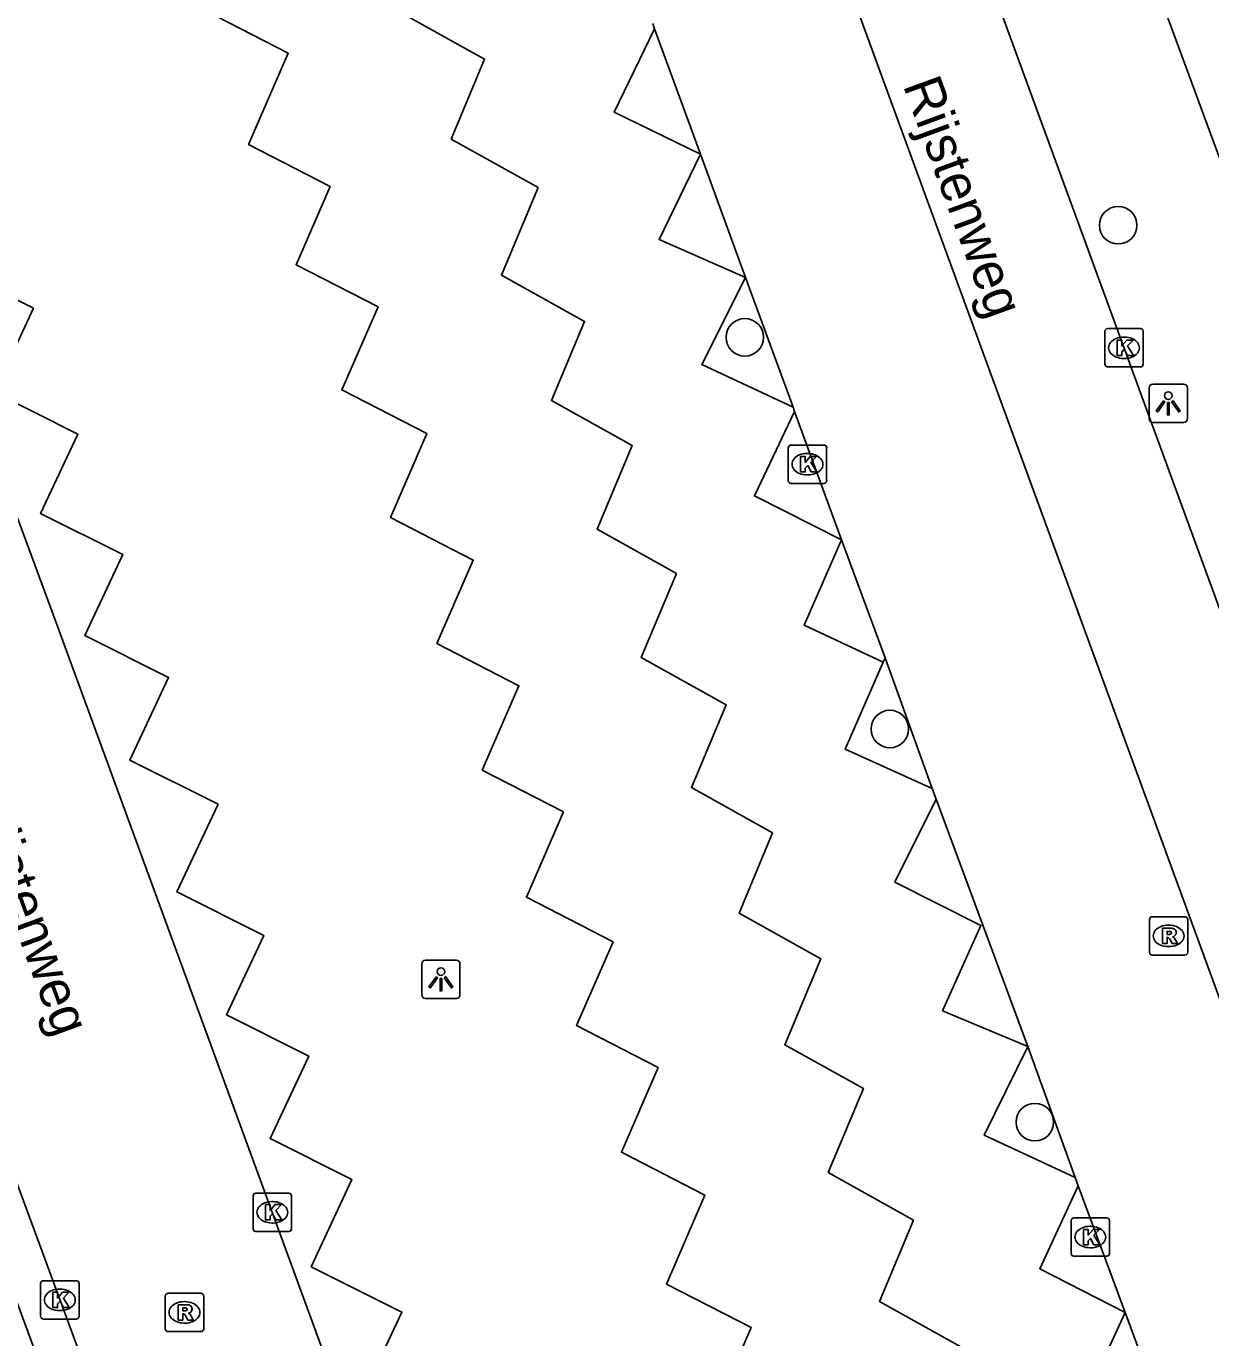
# Model space of a CAD drawing. Extents: x 158087 to 159494, y 382905 to 383981.
# Drawn here: x 159009.25 to 159040.12, y 383055.22 to 383089.39 of the extents above; entities that cross this region are included whole.
import ezdxf

# ---------------------------------------------------------------- set-up
doc = ezdxf.new("R2010")
doc.units = 0
for name, color, linetype in [('IMGEO_Boom', 7, 'Continuous'), ('IMGEO_Fietspad_gesloten', 7, 'Continuous'), ('IMGEO_Haag', 7, 'Continuous'), ('IMGEO_Kolk', 7, 'Continuous'), ('IMGEO_Lichtpunt', 7, 'Continuous'), ('IMGEO_Openbare_ruimte_label', 7, 'Continuous'), ('IMGEO_Parkeervlak_open', 7, 'Continuous'), ('IMGEO_Rijbaan_lokaal_open', 7, 'Continuous'), ('IMGEO_Rioolput', 7, 'Continuous'), ('IMGEO_Voetpad_open', 7, 'Continuous')]:
    doc.layers.add(name, color=color, linetype=linetype)

msp = doc.modelspace()

# ---------------------------------------------------------------- linework, layer by layer
at = {"layer": 'IMGEO_Boom'}
for centre in [(159037.708, 383084.203), (159027.977, 383081.283), (159031.757, 383071.077), (159035.537, 383060.834)]:
    msp.add_circle(centre, 0.489, dxfattribs=at)
at = {"layer": 'IMGEO_Fietspad_gesloten'}
for points in [[(159019.008, 383132.479), (159054.763, 383034.863)], [(159015.626, 383131.206), (159027.244, 383099.827), (159051.483, 383033.66)]]:
    msp.add_lwpolyline(points, dxfattribs=at)
at = {"layer": 'IMGEO_Haag'}
for points in [[(159027.998, 383082.843), (159029.233, 383079.462)], [(159031.633, 383072.927), (159032.862, 383069.528)], [(159035.352, 383062.802), (159036.584, 383059.388)]]:
    msp.add_lwpolyline(points, dxfattribs=at)
at = {"layer": 'IMGEO_Kolk'}
for p, q in [((159037.359, 383080.584), (159037.359, 383081.436)), ((159037.434, 383081.51), (159038.286, 383081.51)), ((159038.36, 383081.436), (159038.36, 383080.584)), ((159037.847, 383081.29), (159037.872, 383081.29)), ((159037.87, 383080.73), (159037.845, 383080.73)), ((159038.286, 383080.51), (159037.434, 383080.51)), ((159029.109, 383077.55), (159029.109, 383078.402)), ((159029.184, 383078.476), (159030.036, 383078.476)), ((159030.11, 383078.402), (159030.11, 383077.55)), ((159029.597, 383078.256), (159029.622, 383078.256)), ((159029.62, 383077.696), (159029.595, 383077.696)), ((159030.036, 383077.476), (159029.184, 383077.476)), ((159015.162, 383058.058), (159015.162, 383058.91)), ((159015.237, 383058.984), (159016.089, 383058.984)), ((159016.163, 383058.91), (159016.163, 383058.058)), ((159015.65, 383058.764), (159015.675, 383058.764)), ((159015.673, 383058.204), (159015.648, 383058.204)), ((159036.481, 383057.414), (159036.481, 383058.266)), ((159036.556, 383058.34), (159037.408, 383058.34)), ((159036.969, 383058.12), (159036.994, 383058.12)), ((159037.482, 383058.266), (159037.482, 383057.414)), ((159016.089, 383057.984), (159015.237, 383057.984)), ((159036.992, 383057.56), (159036.967, 383057.56)), ((159037.408, 383057.34), (159036.556, 383057.34)), ((159009.624, 383055.776), (159009.624, 383056.628)), ((159009.699, 383056.702), (159010.551, 383056.702)), ((159010.112, 383056.482), (159010.137, 383056.482)), ((159010.625, 383056.628), (159010.625, 383055.776)), ((159010.135, 383055.922), (159010.11, 383055.922)), ((159010.551, 383055.702), (159009.699, 383055.702))]:
    msp.add_line(p, q, dxfattribs=at)
for points in [[(159037.359, 383080.584), (159037.359, 383081.436)], [(159037.434, 383081.51), (159038.286, 383081.51)], [(159038.36, 383081.436), (159038.36, 383080.584)], [(159037.68, 383081.21), (159037.803, 383081.21), (159037.803, 383081.059), (159037.933, 383081.21), (159038.097, 383081.21), (159037.951, 383081.059), (159038.104, 383080.81), (159037.952, 383080.81), (159037.867, 383080.974), (159037.803, 383080.907), (159037.803, 383080.81), (159037.68, 383080.81), (159037.68, 383081.21)], [(159038.286, 383080.51), (159037.434, 383080.51)], [(159029.109, 383077.55), (159029.109, 383078.402)], [(159029.184, 383078.476), (159030.036, 383078.476)], [(159030.11, 383078.402), (159030.11, 383077.55)], [(159029.43, 383078.176), (159029.553, 383078.176), (159029.553, 383078.025), (159029.683, 383078.176), (159029.847, 383078.176), (159029.701, 383078.025), (159029.854, 383077.776), (159029.702, 383077.776), (159029.617, 383077.94), (159029.553, 383077.873), (159029.553, 383077.776), (159029.43, 383077.776), (159029.43, 383078.176)], [(159030.036, 383077.476), (159029.184, 383077.476)], [(159015.162, 383058.058), (159015.162, 383058.91)], [(159015.237, 383058.984), (159016.089, 383058.984)], [(159016.163, 383058.91), (159016.163, 383058.058)], [(159015.483, 383058.684), (159015.606, 383058.684), (159015.606, 383058.533), (159015.736, 383058.684), (159015.9, 383058.684), (159015.754, 383058.533), (159015.907, 383058.284), (159015.755, 383058.284), (159015.67, 383058.448), (159015.606, 383058.381), (159015.606, 383058.284), (159015.483, 383058.284), (159015.483, 383058.684)], [(159036.481, 383057.414), (159036.481, 383058.266)], [(159036.556, 383058.34), (159037.408, 383058.34)], [(159037.482, 383058.266), (159037.482, 383057.414)], [(159016.089, 383057.984), (159015.237, 383057.984)], [(159036.802, 383058.04), (159036.925, 383058.04), (159036.925, 383057.889), (159037.055, 383058.04), (159037.219, 383058.04), (159037.073, 383057.889), (159037.226, 383057.64), (159037.074, 383057.64), (159036.989, 383057.804), (159036.925, 383057.737), (159036.925, 383057.64), (159036.802, 383057.64), (159036.802, 383058.04)], [(159037.408, 383057.34), (159036.556, 383057.34)], [(159009.624, 383055.776), (159009.624, 383056.628)], [(159009.699, 383056.702), (159010.551, 383056.702)], [(159010.625, 383056.628), (159010.625, 383055.776)], [(159009.945, 383056.402), (159010.068, 383056.402), (159010.068, 383056.251), (159010.198, 383056.402), (159010.362, 383056.402), (159010.216, 383056.251), (159010.369, 383056.002), (159010.217, 383056.002), (159010.132, 383056.166), (159010.068, 383056.099), (159010.068, 383056.002), (159009.945, 383056.002), (159009.945, 383056.402)], [(159010.551, 383055.702), (159009.699, 383055.702)]]:
    msp.add_lwpolyline(points, dxfattribs=at)
for centre, start, end in [((159037.436, 383081.434), 91.552, 178.448), ((159037.436, 383081.434), 91.552, 178.448), ((159038.284, 383081.434), 1.552, 88.448), ((159038.284, 383081.434), 1.552, 88.448), ((159037.436, 383080.586), 181.552, 268.448), ((159037.436, 383080.586), 181.552, 268.448), ((159038.284, 383080.586), 271.552, 358.448), ((159038.284, 383080.586), 271.552, 358.448), ((159029.186, 383078.4), 91.552, 178.448), ((159029.186, 383078.4), 91.552, 178.448), ((159030.034, 383078.4), 1.552, 88.448), ((159030.034, 383078.4), 1.552, 88.448), ((159029.186, 383077.552), 181.552, 268.448), ((159029.186, 383077.552), 181.552, 268.448), ((159030.034, 383077.552), 271.552, 358.448), ((159030.034, 383077.552), 271.552, 358.448), ((159015.239, 383058.908), 91.552, 178.448), ((159015.239, 383058.908), 91.552, 178.448), ((159016.087, 383058.908), 1.552, 88.448), ((159016.087, 383058.908), 1.552, 88.448), ((159036.558, 383058.264), 91.552, 178.448), ((159036.558, 383058.264), 91.552, 178.448), ((159037.406, 383058.264), 1.552, 88.448), ((159037.406, 383058.264), 1.552, 88.448), ((159015.239, 383058.06), 181.552, 268.448), ((159015.239, 383058.06), 181.552, 268.448), ((159016.087, 383058.06), 271.552, 358.448), ((159016.087, 383058.06), 271.552, 358.448), ((159036.558, 383057.416), 181.552, 268.448), ((159036.558, 383057.416), 181.552, 268.448), ((159037.406, 383057.416), 271.552, 358.448), ((159037.406, 383057.416), 271.552, 358.448), ((159009.701, 383056.626), 91.552, 178.448), ((159009.701, 383056.626), 91.552, 178.448), ((159010.549, 383056.626), 1.552, 88.448), ((159010.549, 383056.626), 1.552, 88.448), ((159009.701, 383055.778), 181.552, 268.448), ((159009.701, 383055.778), 181.552, 268.448), ((159010.549, 383055.778), 271.552, 358.448), ((159010.549, 383055.778), 271.552, 358.448)]:
    msp.add_arc(centre, 0.0765, start, end, dxfattribs=at)
for centre, major_axis, ratio, start_param, end_param in [((159037.846, 383081.01), (-0.387, 0.002), 0.722429, 4.712389, 7.853982), ((159037.871, 383081.01), (-0.39, 0.002), 0.717154, 1.570796, 4.712389), ((159029.596, 383077.976), (-0.387, 0.002), 0.722429, 4.712389, 7.853982), ((159029.621, 383077.976), (-0.39, 0.002), 0.717154, 1.570796, 4.712389), ((159015.649, 383058.484), (-0.387, 0.002), 0.722429, 4.712389, 7.853982), ((159015.674, 383058.484), (-0.39, 0.002), 0.717154, 1.570796, 4.712389), ((159036.968, 383057.84), (-0.387, 0.002), 0.722429, 4.712389, 7.853982), ((159036.993, 383057.84), (-0.39, 0.002), 0.717154, 1.570796, 4.712389), ((159010.111, 383056.202), (-0.387, 0.002), 0.722429, 4.712389, 7.853982), ((159010.136, 383056.202), (-0.39, 0.002), 0.717154, 1.570796, 4.712389)]:
    msp.add_ellipse(centre, major_axis=major_axis, ratio=ratio, start_param=start_param, end_param=end_param, dxfattribs=at)
at = {"layer": 'IMGEO_Lichtpunt'}
for p, q in [((159039.417, 383080.06), (159038.609, 383080.06)), ((159039.417, 383080.06), (159038.609, 383080.06)), ((159038.515, 383079.965), (159038.515, 383079.158)), ((159038.515, 383079.965), (159038.515, 383079.158)), ((159039.511, 383079.158), (159039.511, 383079.965)), ((159039.511, 383079.158), (159039.511, 383079.965)), ((159038.609, 383079.064), (159039.417, 383079.064)), ((159038.609, 383079.064), (159039.417, 383079.064)), ((159019.557, 383064.958), (159019.557, 383064.151)), ((159019.557, 383064.958), (159019.557, 383064.151)), ((159020.459, 383065.053), (159019.651, 383065.053)), ((159020.459, 383065.053), (159019.651, 383065.053)), ((159020.553, 383064.151), (159020.553, 383064.958)), ((159020.553, 383064.151), (159020.553, 383064.958)), ((159019.651, 383064.057), (159020.459, 383064.057)), ((159019.651, 383064.057), (159020.459, 383064.057))]:
    msp.add_line(p, q, dxfattribs=at)
for points in [[(159038.889, 383079.629), (159038.928, 383079.601), (159038.74, 383079.339), (159038.702, 383079.366), (159038.889, 383079.629)], [(159038.991, 383079.581), (159039.038, 383079.581), (159039.038, 383079.259), (159038.991, 383079.259), (159038.991, 383079.581)], [(159039.101, 383079.601), (159039.139, 383079.628), (159039.326, 383079.366), (159039.287, 383079.338), (159039.101, 383079.601)], [(159019.931, 383064.622), (159019.97, 383064.594), (159019.782, 383064.332), (159019.744, 383064.359), (159019.931, 383064.622)], [(159020.143, 383064.594), (159020.181, 383064.621), (159020.368, 383064.359), (159020.329, 383064.331), (159020.143, 383064.594)], [(159020.033, 383064.574), (159020.08, 383064.574), (159020.08, 383064.252), (159020.033, 383064.252), (159020.033, 383064.574)]]:
    msp.add_lwpolyline(points, dxfattribs=at)
for centre in [(159039.014, 383079.763), (159020.056, 383064.756)]:
    msp.add_circle(centre, 0.0994, dxfattribs=at)
for centre, start, end in [((159038.609, 383079.965), 90, 180), ((159038.609, 383079.965), 90, 180), ((159039.417, 383079.965), 0, 90), ((159039.417, 383079.965), 0, 90), ((159038.609, 383079.158), 180, 270), ((159038.609, 383079.158), 180, 270), ((159039.417, 383079.158), 270, 0), ((159039.417, 383079.158), 270, 360), ((159019.651, 383064.958), 90, 180), ((159019.651, 383064.958), 90, 180), ((159020.459, 383064.958), 0, 90), ((159020.459, 383064.958), 0, 90), ((159019.651, 383064.151), 180, 270), ((159019.651, 383064.151), 180, 270), ((159020.459, 383064.151), 270, 0), ((159020.459, 383064.151), 270, 360)]:
    msp.add_arc(centre, 0.0946, start, end, dxfattribs=at)
at = {"layer": 'IMGEO_Parkeervlak_open'}
for points in [[(159025.576, 383089.458), (159025.627, 383089.318)], [(159027.998, 383082.843), (159026.854, 383080.574), (159029.233, 383079.462)], [(159029.233, 383079.462), (159029.273, 383079.352)], [(159031.587, 383072.822), (159030.589, 383070.553), (159032.862, 383069.528)], [(159032.862, 383069.528), (159032.965, 383069.25)], [(159035.352, 383062.802), (159034.218, 383060.491), (159036.584, 383059.388)], [(159036.584, 383059.388), (159036.663, 383059.174)]]:
    msp.add_lwpolyline(points, dxfattribs=at)
at = {"layer": 'IMGEO_Rijbaan_lokaal_open'}
for points in [[(158989.496, 383130.166), (158989.507, 383130.115), (158993.547, 383118.852), (159000, 383101.106), (159000.486, 383099.77), (159004.399, 383089.064), (159010.016, 383073.897), (159017.762, 383052.749), (159024.745, 383033.951), (159029.515, 383020.822)], [(159013.895, 383089.803), (159016.076, 383088.683), (159015.043, 383086.305), (159017.17, 383085.212), (159016.284, 383083.174), (159018.417, 383082.078), (159017.476, 383079.913), (159019.693, 383078.774), (159018.743, 383076.588), (159020.899, 383075.48), (159019.952, 383073.302), (159022.089, 383072.204), (159021.133, 383070.005), (159023.25, 383068.917), (159022.283, 383066.694), (159024.543, 383065.533), (159023.593, 383063.348), (159025.723, 383062.254), (159024.764, 383060.048), (159026.939, 383058.931), (159025.933, 383056.616), (159028.145, 383055.48), (159027.183, 383053.267)], [(159033.687, 383054.933), (159031.485, 383056.162), (159032.372, 383058.28), (159030.15, 383059.52), (159031.066, 383061.707), (159029.019, 383062.849), (159029.958, 383065.091), (159027.826, 383066.28), (159028.701, 383068.369), (159026.584, 383069.55), (159027.488, 383071.708), (159025.28, 383072.94), (159026.196, 383075.127), (159024.129, 383076.28), (159025.042, 383078.461), (159022.938, 383079.635), (159023.801, 383081.695), (159021.636, 383082.903), (159022.591, 383085.183), (159020.324, 383086.448), (159021.195, 383088.528), (159019.1, 383089.697)], [(159018.031, 383053.735), (159019.04, 383055.883), (159016.672, 383057.067), (159017.738, 383059.337), (159015.604, 383060.404), (159016.614, 383062.556), (159014.469, 383063.629), (159015.441, 383065.7), (159013.175, 383066.833), (159014.248, 383069.118), (159011.947, 383070.269), (159012.957, 383072.42), (159010.773, 383073.512), (159011.765, 383075.625), (159009.624, 383076.695), (159010.595, 383078.763), (159008.409, 383079.856), (159009.435, 383082.042), (159007.189, 383083.165)], [(159019.666, 383030.258), (159014.295, 383044.868), (159010.659, 383054.753), (159005.874, 383067.711), (159001.376, 383079.933)]]:
    msp.add_lwpolyline(points, dxfattribs=at)
at = {"layer": 'IMGEO_Rioolput'}
for p, q in [((159038.522, 383065.26), (159038.522, 383066.112)), ((159038.597, 383066.186), (159039.449, 383066.186)), ((159039.523, 383066.112), (159039.523, 383065.26)), ((159039.01, 383065.966), (159039.035, 383065.966)), ((159039.033, 383065.406), (159039.008, 383065.406)), ((159039.449, 383065.186), (159038.597, 383065.186)), ((159012.873, 383055.451), (159012.873, 383056.303)), ((159012.948, 383056.377), (159013.8, 383056.377)), ((159013.361, 383056.157), (159013.386, 383056.157)), ((159013.874, 383056.303), (159013.874, 383055.451)), ((159013.384, 383055.597), (159013.359, 383055.597)), ((159013.8, 383055.377), (159012.948, 383055.377))]:
    msp.add_line(p, q, dxfattribs=at)
for points in [[(159038.522, 383065.26), (159038.522, 383066.112)], [(159038.597, 383066.186), (159039.449, 383066.186)], [(159039.523, 383066.112), (159039.523, 383065.26)], [(159039.111, 383065.884), (159038.859, 383065.886), (159038.859, 383065.486)], [(159038.859, 383065.486), (159038.983, 383065.486), (159038.983, 383065.648), (159038.994, 383065.648)], [(159039.037, 383065.805), (159038.983, 383065.805), (159038.983, 383065.724)], [(159038.983, 383065.724), (159039.035, 383065.724)], [(159039.041, 383065.619), (159039.112, 383065.486), (159039.252, 383065.486), (159039.187, 383065.612)], [(159039.449, 383065.186), (159038.597, 383065.186)], [(159012.873, 383055.451), (159012.873, 383056.303)], [(159012.948, 383056.377), (159013.8, 383056.377)], [(159013.462, 383056.075), (159013.21, 383056.077), (159013.21, 383055.677)], [(159013.874, 383056.303), (159013.874, 383055.451)], [(159013.21, 383055.677), (159013.334, 383055.677), (159013.334, 383055.839), (159013.345, 383055.839)], [(159013.388, 383055.996), (159013.334, 383055.996), (159013.334, 383055.915)], [(159013.334, 383055.915), (159013.386, 383055.915)], [(159013.392, 383055.81), (159013.463, 383055.677), (159013.603, 383055.677), (159013.538, 383055.803)], [(159013.8, 383055.377), (159012.948, 383055.377)]]:
    msp.add_lwpolyline(points, dxfattribs=at)
for centre, radius, start, end in [((159038.599, 383066.11), 0.0765, 91.552, 178.448), ((159038.599, 383066.11), 0.0765, 91.552, 178.448), ((159039.447, 383066.11), 0.0765, 1.552, 88.448), ((159039.447, 383066.11), 0.0765, 1.552, 88.448), ((159038.993, 383065.595), 0.0533, 26.0293, 88.6989), ((159039.019, 383065.913), 0.19, 274.7715, 282.9687), ((159039.043, 383065.709), 0.0964, 77.0061, 93.1865), ((159039.057, 383065.766), 0.0378, 276.6634, 79.6772), ((159039.11, 383065.774), 0.109, 350.3612, 89.416), ((159039.108, 383065.774), 0.112, 277.5842, 350.9817), ((159039.092, 383065.559), 0.108, 29.5134, 73.7905), ((159038.599, 383065.262), 0.0765, 181.552, 268.448), ((159038.599, 383065.262), 0.0765, 181.552, 268.448), ((159039.447, 383065.262), 0.0765, 271.552, 358.448), ((159039.447, 383065.262), 0.0765, 271.552, 358.448), ((159012.95, 383056.301), 0.0765, 91.552, 178.448), ((159012.95, 383056.301), 0.0765, 91.552, 178.448), ((159013.461, 383055.965), 0.109, 350.3612, 89.416), ((159013.798, 383056.301), 0.0765, 1.552, 88.448), ((159013.798, 383056.301), 0.0765, 1.552, 88.448), ((159013.344, 383055.786), 0.0533, 26.0293, 88.6989), ((159013.37, 383056.104), 0.19, 274.7715, 282.9687), ((159013.394, 383055.9), 0.0964, 77.0061, 93.1865), ((159013.408, 383055.957), 0.0378, 276.6634, 79.6772), ((159013.459, 383055.965), 0.112, 277.5842, 350.9817), ((159013.443, 383055.75), 0.108, 29.5134, 73.7905), ((159012.95, 383055.453), 0.0765, 181.552, 268.448), ((159012.95, 383055.453), 0.0765, 181.552, 268.448), ((159013.798, 383055.453), 0.0765, 271.552, 358.448), ((159013.798, 383055.453), 0.0765, 271.552, 358.448)]:
    msp.add_arc(centre, radius, start, end, dxfattribs=at)
for centre, major_axis, ratio, start_param, end_param in [((159039.009, 383065.686), (-0.387, 0.002), 0.722429, 4.712389, 7.853982), ((159039.034, 383065.686), (-0.39, 0.002), 0.717154, 1.570796, 4.712389), ((159013.36, 383055.877), (-0.387, 0.002), 0.722429, 4.712389, 7.853982), ((159013.385, 383055.877), (-0.39, 0.002), 0.717154, 1.570796, 4.712389)]:
    msp.add_ellipse(centre, major_axis=major_axis, ratio=ratio, start_param=start_param, end_param=end_param, dxfattribs=at)
at = {"layer": 'IMGEO_Voetpad_open'}
for points in [[(159010.268, 383168.562), (159011.662, 383164.733), (159020.287, 383140.814), (159034.214, 383102.582), (159046.708, 383068.727), (159049.345, 383061.497), (159054.421, 383047.583)], [(159025.627, 383089.318), (159024.569, 383087.153), (159026.822, 383086.055)], [(159026.822, 383086.055), (159025.627, 383089.318)], [(159026.822, 383086.055), (159025.744, 383083.827), (159027.998, 383082.843)], [(159027.998, 383082.843), (159026.822, 383086.055)], [(159018.685, 383029.891), (159013.433, 383044.02), (159010.822, 383051.232), (159000.349, 383079.556)], [(159029.273, 383079.352), (159028.228, 383077.152), (159030.501, 383076.007)], [(159030.501, 383076.007), (159029.273, 383079.352)], [(159030.501, 383076.007), (159029.525, 383073.779), (159031.587, 383072.822)], [(159031.633, 383072.927), (159030.501, 383076.007)], [(159031.587, 383072.822), (159031.633, 383072.927)], [(159032.965, 383069.25), (159031.887, 383067.088), (159034.132, 383065.961), (159033.131, 383063.738), (159035.352, 383062.802)], [(159035.352, 383062.802), (159032.965, 383069.25)], [(159036.663, 383059.174), (159035.663, 383057.013), (159037.887, 383055.873)], [(159037.887, 383055.873), (159036.663, 383059.174)], [(159037.887, 383055.873), (159036.878, 383053.681), (159038.93, 383052.687)], [(159039.009, 383052.846), (159037.887, 383055.873)]]:
    msp.add_lwpolyline(points, dxfattribs=at)

# ---------------------------------------------------------------- texts
at = {"layer": 'IMGEO_Openbare_ruimte_label'}
for rotation, p in [(290.1202, (159032.091, 383087.852)), (290.1739, (159007.761, 383069.147))]:
    msp.add_text('Rijstenweg', height=1, rotation=rotation, dxfattribs=at).set_placement(p)

doc.saveas('drawing.dxf')
